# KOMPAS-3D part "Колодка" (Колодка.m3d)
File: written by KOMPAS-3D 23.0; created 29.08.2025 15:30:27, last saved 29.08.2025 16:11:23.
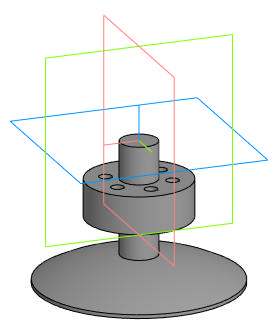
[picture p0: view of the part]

Document properties: Автор: Lost; Полное имя файла: C:\Users\Lost\Desktop\Вариант 1\Колодка.m3d

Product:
- Part/product: Колодка
    Масса: 0.137353

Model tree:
1. Эскиз:3  (with: Элемент вращения:2)  (labels: C:\Users\Lost\Desktop\Вариант 1\Сборка колеса.a3d)
2. Элемент выдавливания:1
     Расстояние 1 = 20
3. Эскиз:5  (with: Элемент выдавливания:1)
4. Элемент вращения:1
     Угол 1 = 360
5. Эскиз:6  (with: Элемент выдавливания:1)
6. Элемент вращения:2
     Угол 1 = 360
7. Эскиз:7  (with: Элемент выдавливания:1)  (labels: C:\Users\Lost\Desktop\Вариант 1\Сборка колеса.a3d)
8. Элемент выдавливания:4  (with: Элемент вращения:2)
     Расстояние 2 = 2.10404
9. Элемент выдавливания:5  (with: Элемент выдавливания:1, Элемент выдавливания:2)  (labels: C:\Users\Lost\Desktop\Вариант 1\Сборка колеса.a3d)
     Расстояние 1 = 10
10. Элемент выдавливания:6  (with: Элемент вращения:2)  (labels: C:\Users\Lost\Desktop\Вариант 1\Сборка колеса.a3d)
     Расстояние 1 = 7.89596
11. Элемент выдавливания:8  (with: Элемент вращения:2)
     Расстояние 1 = 0.895964
12. Элемент выдавливания:11  (with: Элемент вращения:2, Элемент выдавливания:1)  (labels: C:\Users\Lost\Desktop\Вариант 1\Сборка колеса.a3d)
     Расстояние 2 = 0.895964

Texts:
  Смещение (% от длины кривой)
